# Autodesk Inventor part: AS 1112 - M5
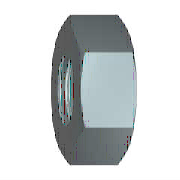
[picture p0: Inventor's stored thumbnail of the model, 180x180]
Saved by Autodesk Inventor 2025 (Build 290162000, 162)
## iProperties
Created: 2024-01
Part Number: AS 1112 - M5
Material: Acciaio, Dolce
Description: Dadi esagonali metrici ISO, inclusi dadi sottili, dadi con intaglio e dadi a corona
Document SubType Name: Modeling
Standard: AS 1112
Designer: R5800u
Standards Organization: AS
Language: it-IT
Size Designation: M5
Categories: <MemberInstance><Categories><Category DisplayName="Elementi di fissaggio" InternalName="e4da775c-781d-43d5-af7c-5136215cf5a6" Mnemonic="FSTN"><Category DisplayN
Density: 7.85 g/cm^3
Appearance: Semilucidato
IsCustomPart: 0
Author: R5800u
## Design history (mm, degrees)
workaxis "Work Axis1"
workplane "Work Plane1"
sketch "Schizzo1"
  geometry: L1 (-4.619, 0)-(-2.309, 4); L2 (-2.309, 4)-(2.309, 4); L3 (2.309, 4)-(4.619, 0); L4 (4.619, 0)-(2.309, -4); L5 (2.309, -4)-(-2.309, -4); L6 (-2.309, -4)-(-4.619, 0); 2 further points
  constraints: 12 end point, 1 coincident, 1 horizontal, 11 other
  dimensions: "d0" = 9.2376 distance of L3.end L1.start (= 1.1547 x SW)
extrude "Corpo" new body sketch "Schizzo1" distance "d1" = 3 (= KOH); taper "d2" = 0 deg
revolve "Smusso1" stored, may be unused: angle "d7" = 90 deg
sketch "Schizzo3"
  geometry: A1 r 4 centre (0, 0) between (-2, -3.464) and (2, -3.464) reference; 1 further point
  constraints: 1 coincident
hole "Filettatura" sketch "Schizzo3" diameter "d25" = 4.134; stored, may be unused: countersink angle "d29" = 82 deg, drill point angle "d31" = 118 deg; dims "d26" = 6, "d27" = 4, "d28" = 2, "d30" = 8
body "Solid1"
chamfer "Smusso2" distance "d8" = 0.43301 (= -0.5 x GD1 + 0.5 x NND); stored, may be unused: angle "d9" = 30 deg, second distance "d40" = 0.43301 (= -0.5 x GD1 + 0.5 x NND)
chamfer "Smusso3" distance "d10" = 0.43301 (= -0.5 x GD1 + 0.5 x NND); stored, may be unused: angle "d11" = 30 deg, second distance "d41" = 0.43301 (= -0.5 x GD1 + 0.5 x NND)
sketch "Schizzo2"
  geometry: L1 (0, 2.309)-(0, 4.619) reference; L2 (0, 4.619)-(3, 4.619) reference; L3 (3, 2.309)-(3, 4.619) reference; L4 (-0.6, 0)-(3.6, 0) reference; L5 (0.357, 4.619)-(0, 4); L6 (2.643, 4.619)-(3, 4)
  constraints: 4 end point, 4 point on line
  dimensions: "d3" = 30 deg angle of L1 L5 (= ANG1); "d4" = 30 deg angle of L3 L6 (= ANG2); "d5" = 8 diameter of L5.end L4 (= SW0); "d6" = 8 diameter of L6.end L4 (= SW01)
other parameters: "ANG1" = 30 deg [user parameter; used in 1 equation term], "ANG2" = 30 deg [user parameter; used in 1 equation term], "NND" = 5 [user parameter; used in 4 equation terms], "KOH" = 3 [user parameter; used in 1 equation term], "SW" = 8 [user parameter; used in 4 equation terms], "SW0" = 8 (= SW) [user parameter; used in 1 equation term], "SW01" = 8 (= SW) [user parameter; used in 1 equation term], "GD1" = 4.13397 (computed from THREADDIA, PTC, TOA) [user parameter; used in 4 equation terms], "d13" = 0, "d14" = 0, "d39" = 0, "d42" = 0, "GUL" = 0.43301 (= 0.541266 x PTC) [user parameter], "TPU" = 12.5 (computed from PTC) [user parameter], "THREADDIA" = 5 [user parameter; used in 1 equation term], "TOA" = 30 deg [user parameter; used in 1 equation term], "PTC" = 0.8 [user parameter; used in 4 equation terms], "E0" = 9.24 (= 1.155 x SW) [user parameter], "GAL" = 0.43301 (= 0.541266 x PTC) [user parameter]
